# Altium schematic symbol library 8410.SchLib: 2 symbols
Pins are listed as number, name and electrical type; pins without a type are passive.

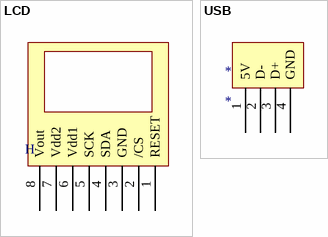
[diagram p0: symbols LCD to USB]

## LCD
designator H  (value not drawn)
pins: 1 RESET, 2 /CS, 3 GND, 4 SDA, 5 SCK, 6 Vdd1, 7 Vdd2, 8 Vout

## USB
designator *
pins: 1 5V, 2 D-, 3 D+, 4 GND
